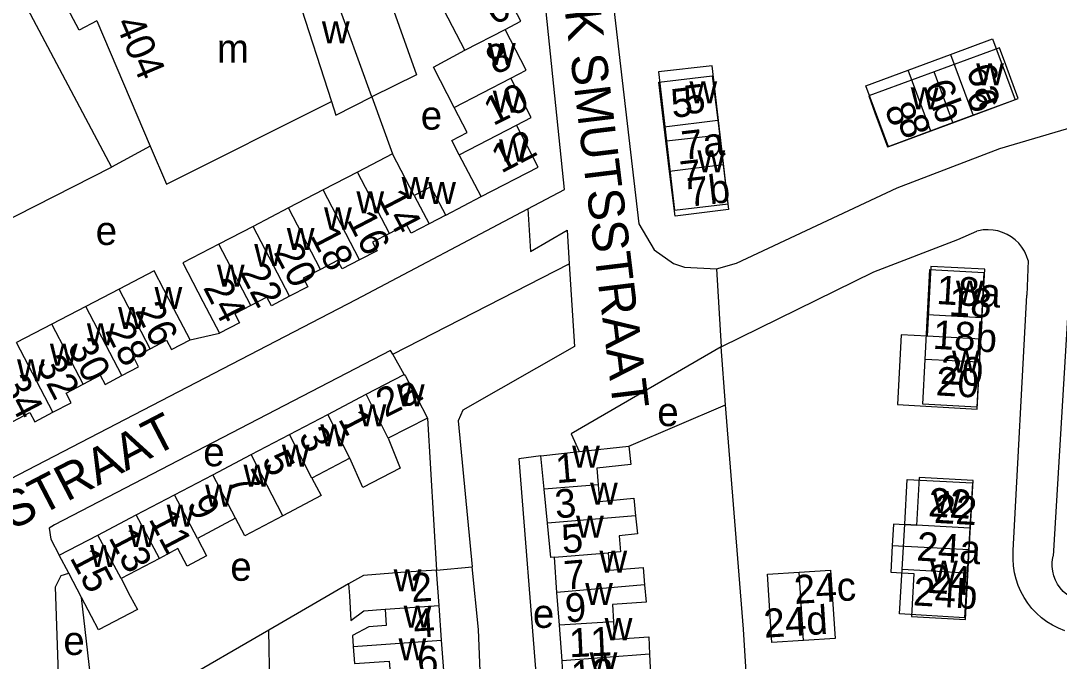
# Model space of a CAD drawing. Extents: x 163012 to 165277, y 382513 to 383987.
# Drawn here: x 163588.9 to 163733.4, y 383626.1 to 383715.3 of the extents above; entities that cross this region are included whole.
import ezdxf

# ---------------------------------------------------------------- set-up
doc = ezdxf.new("R2010")
doc.units = 0
for name, color, linetype in [('BLT_Basislijn', 7, 'Continuous'), ('BLT_Bebouwing', 7, 'Continuous'), ('BLT_Centroide', 7, 'Continuous'), ('BLT_Huisnummer', 7, 'Continuous'), ('BLT_Huisnummer_ tussenligend', 7, 'Continuous'), ('BLT_Huisnummer_zonder_bebouwing', 7, 'Continuous'), ('BLT_Onderverdeling_panden', 7, 'Continuous'), ('BLT_Plantopo', 7, 'Continuous'), ('BLT_Straatnaam', 7, 'Continuous'), ('BLT_Vlakafsluiter', 7, 'Continuous')]:
    doc.layers.add(name, color=color, linetype=linetype)

msp = doc.modelspace()

# ---------------------------------------------------------------- linework, layer by layer
at = {"layer": 'BLT_Basislijn'}
for p, q in [((163582.55, 383730.64), (163601.48, 383694.92)), ((163637.73, 383704.71), (163640.61, 383696.76)), ((163606.89, 383697.83), (163601.48, 383694.92)), ((163568.14, 383677.94), (163601.48, 383694.92)), ((163648.01, 383688.22), (163652.93, 383690.8)), ((163735.53, 383690.22), (163732.58, 383640.71)), ((163659.45, 383689.12), (163659.84, 383683.15)), ((163664.9, 383686.14), (163665.21, 383681.42)), ((163719.31, 383684.81), (163721.97, 383686.01)), ((163640.64, 383668.85), (163665.21, 383681.42)), ((163729.11, 383681.93), (163728.9, 383677.07)), ((163727.03, 383641.54), (163728.9, 383677.07)), ((163612.42, 383670.85), (163616.52, 383671.78)), ((163686.95, 383661.81), (163686.38, 383669.89)), ((163650.42, 383661.05), (163649.73, 383659.6)), ((163673.49, 383656.06), (163686.95, 383661.81)), ((163645.49, 383659.96), (163646.75, 383638.77)), ((163649.73, 383659.6), (163651.72, 383639.24)), ((163646.75, 383638.77), (163651.72, 383639.24)), ((163634.5, 383636.86), (163623.38, 383630.43)), ((163598.99, 383620.36), (163597.31, 383634.97)), ((163623.38, 383630.43), (163606.39, 383620.61)), ((163624.48, 383570.81), (163623.38, 383630.43))]:
    msp.add_line(p, q, dxfattribs=at)
for points in [[(163685.7, 383680.74), (163688.5, 383681.55), (163710.87, 383692.04), (163725.15, 383697.49), (163749.05, 383704.56), (163761.01, 383707), (163763.71, 383708.64), (163765.63, 383712.11), (163765.51, 383716.48), (163759.18, 383758.11)], [(163667.93, 383746.93), (163674.89, 383687.03), (163677.03, 383683.37), (163679.74, 383681.51), (163681.27, 383680.98), (163685.7, 383680.74)], [(163659.45, 383689.12), (163664.53, 383691.81), (163659.91, 383736.81)], [(163646.24, 383730.06), (163637.73, 383726.14), (163637.69, 383725.42), (163643.96, 383707.78), (163637.73, 383704.71)], [(163576.22, 383645.71), (163635.54, 383676.46), (163659.45, 383689.12)], [(163729.11, 383681.93), (163728.89, 383682.58), (163728.59, 383683.19), (163728.22, 383683.77), (163727.79, 383684.3), (163727.3, 383684.78), (163726.75, 383685.19), (163726.16, 383685.54), (163725.54, 383685.82), (163724.88, 383686.03), (163724.21, 383686.15), (163723.53, 383686.2), (163722.84, 383686.17), (163722.17, 383686.06), (163721.97, 383686.01)], [(163686.38, 383669.89), (163707.62, 383680.34), (163719.31, 383684.81)], [(163665.21, 383681.42), (163665.96, 383669.91), (163650.42, 383661.05)], [(163686.38, 383669.89), (163665.49, 383657.78), (163666.59, 383655.31)], [(163640.33, 383669.39), (163593.57, 383645.08), (163592.83, 383644.64), (163593.05, 383643.11), (163594.21, 383640.86)], [(163640.64, 383668.85), (163640.33, 383669.39)], [(163642.25, 383666.05), (163640.64, 383668.85)], [(163691.35, 383595.34), (163691.29, 383601.54), (163689.46, 383630.56), (163686.95, 383661.81)], [(163661.25, 383654.72), (163658.19, 383654.3), (163660.65, 383623.29), (163661.65, 383594.45)], [(163734.19, 383630.33), (163733.33, 383630.68), (163732.49, 383631.11), (163731.7, 383631.6), (163730.96, 383632.16), (163730.26, 383632.78), (163729.62, 383633.46), (163729.05, 383634.19), (163728.53, 383634.97), (163728.09, 383635.79), (163727.71, 383636.65), (163727.42, 383637.53), (163727.19, 383638.43), (163727.05, 383639.36), (163726.99, 383640.29), (163727, 383641.22), (163727.03, 383641.54)], [(163738.09, 383634.39), (163737.45, 383634.36), (163736.81, 383634.42), (163736.18, 383634.56), (163735.58, 383634.77), (163735, 383635.06), (163734.47, 383635.41), (163733.98, 383635.83), (163733.55, 383636.31), (163733.19, 383636.84), (163732.89, 383637.4), (163732.66, 383638), (163732.51, 383638.63), (163732.44, 383639.27), (163732.45, 383639.91), (163732.54, 383640.54), (163732.58, 383640.71)], [(163652.49, 383543.85), (163653.68, 383563.38), (163653.68, 383602.63), (163652.56, 383630.51), (163651.72, 383639.24)], [(163594.27, 383620.21), (163593.69, 383636.45), (163594.48, 383638.03), (163595.53, 383638.36)]]:
    msp.add_lwpolyline(points, dxfattribs=at)
at = {"layer": 'BLT_Bebouwing'}
for p, q in [((163596.99, 383714), (163586.94, 383733)), ((163599.44, 383715.3), (163596.99, 383714)), ((163599.44, 383715.3), (163606.89, 383697.83)), ((163640.61, 383696.76), (163635.74, 383694.23)), ((163643.63, 383690.97), (163640.61, 383696.76)), ((163635.74, 383694.23), (163630.95, 383691.73)), ((163630.95, 383691.73), (163626.13, 383689.22)), ((163626.13, 383689.22), (163621.21, 383686.66)), ((163648.01, 383688.22), (163645.69, 383687.01)), ((163621.21, 383686.66), (163616.43, 383684.17)), ((163602.54, 383677.93), (163597.91, 383675.52)), ((163597.91, 383675.52), (163593.19, 383673.06)), ((163593.19, 383673.06), (163588.27, 383670.5)), ((163636.96, 383663.27), (163642.25, 383666.05)), ((163631.62, 383660.47), (163636.96, 383663.27)), ((163644.02, 383662.75), (163645.49, 383659.96)), ((163626.27, 383657.67), (163631.62, 383660.47)), ((163645.49, 383659.96), (163640, 383657.18)), ((163620.93, 383654.87), (163626.27, 383657.67)), ((163661.25, 383654.72), (163666.59, 383655.31)), ((163666.59, 383655.31), (163673.49, 383656.06)), ((163615.59, 383652.07), (163620.93, 383654.87)), ((163634.69, 383654.39), (163629.38, 383651.59)), ((163661.71, 383650.07), (163661.25, 383654.72)), ((163610.25, 383649.27), (163615.59, 383652.07)), ((163604.91, 383646.47), (163610.25, 383649.27)), ((163662.17, 383645.32), (163661.71, 383650.07)), ((163599.57, 383643.67), (163604.91, 383646.47)), ((163618.76, 383646), (163613.45, 383643.2)), ((163594.21, 383640.86), (163599.57, 383643.67)), ((163595.53, 383638.36), (163594.21, 383640.86)), ((163663.5, 383635.68), (163663.14, 383640.58)), ((163608.15, 383640.41), (163602.84, 383637.61)), ((163647.1, 383633.86), (163646.75, 383638.77)), ((163663.84, 383631.13), (163663.5, 383635.68)), ((163647.44, 383629.02), (163647.1, 383633.86)), ((163664.21, 383626.15), (163663.84, 383631.13))]:
    msp.add_line(p, q, dxfattribs=at)
for points in [[(163637.73, 383704.71), (163630.85, 383723.71), (163626.49, 383721.47)], [(163656.27, 383714.09), (163658.46, 383715.22), (163655.59, 383720.75)], [(163650.67, 383711.19), (163647.8, 383716.73), (163649.84, 383717.79)], [(163657.07, 383707.3), (163659.21, 383708.41), (163656.27, 383714.09)], [(163718.61, 383701.12), (163727.72, 383704.48), (163725.99, 383709.17), (163725.12, 383711.53), (163716.01, 383708.18)], [(163649.21, 383703.22), (163646.32, 383708.81), (163650.67, 383711.19)], [(163686.22, 383699.42), (163685.1, 383709.04), (163677.64, 383708.17), (163678.76, 383698.55)], [(163657.85, 383700.74), (163659.91, 383701.81), (163657.07, 383707.3)], [(163716.01, 383708.18), (163706.9, 383704.82), (163707.77, 383702.46), (163709.5, 383697.76), (163718.61, 383701.12)], [(163632.12, 383704.04), (163632.73, 383702.14), (163637.73, 383704.71)], [(163606.89, 383697.83), (163609.13, 383692.55), (163632.12, 383704.04)], [(163649.91, 383696.63), (163648.87, 383698.63), (163651.02, 383699.74), (163649.21, 383703.22)], [(163652.93, 383690.8), (163660.87, 383694.91), (163657.85, 383700.74)], [(163678.76, 383698.55), (163679.88, 383688.93), (163687.34, 383689.8), (163686.22, 383699.42)], [(163652.93, 383690.8), (163649.91, 383696.63)], [(163648.01, 383688.22), (163645.95, 383692.17), (163643.63, 383690.97)], [(163645.69, 383687.01), (163643.19, 383685.71), (163642.55, 383686.92), (163640.19, 383685.69)], [(163640.19, 383685.69), (163637.83, 383684.46), (163638.45, 383683.26), (163636.02, 383681.99)], [(163616.43, 383684.17), (163611.43, 383681.57), (163614.21, 383676.22), (163616.52, 383671.78)], [(163636.02, 383681.99), (163633.59, 383680.73), (163632.97, 383681.92), (163630.58, 383680.67)], [(163722.52, 383670.95), (163723.06, 383680.68), (163715.57, 383681.09), (163715.03, 383671.36)], [(163612.42, 383670.85), (163610.11, 383675.29), (163607.41, 383680.47), (163602.54, 383677.93)], [(163630.58, 383680.67), (163628.19, 383679.43), (163628.81, 383678.24), (163626.27, 383676.92)], [(163626.27, 383676.92), (163623.74, 383675.6), (163623.12, 383676.8), (163620.88, 383675.63)], [(163620.88, 383675.63), (163618.64, 383674.46), (163619.29, 383673.23), (163616.52, 383671.78)], [(163715.03, 383671.36), (163711.44, 383671.56), (163710.91, 383661.83), (163721.98, 383661.22), (163722.52, 383670.95)], [(163602.93, 383665.87), (163605.27, 383667.09), (163604.58, 383668.42), (163606.87, 383669.61)], [(163606.87, 383669.61), (163609.15, 383670.8), (163609.83, 383669.5), (163612.42, 383670.85)], [(163597.55, 383664.68), (163599.93, 383665.92), (163600.59, 383664.65), (163602.93, 383665.87)], [(163642.25, 383666.05), (163642.42, 383665.78), (163644.02, 383662.75)], [(163593.34, 383660.77), (163595.87, 383662.09), (163595.17, 383663.45), (163597.55, 383664.68)], [(163587.76, 383659.48), (163590.14, 383660.73), (163590.8, 383659.45), (163593.34, 383660.77)], [(163640, 383657.18), (163641.69, 383653), (163636.49, 383650.28), (163634.69, 383654.39)], [(163673.49, 383656.06), (163673.78, 383653.48), (163669.05, 383652.99), (163669.24, 383650.67)], [(163629.38, 383651.59), (163630.66, 383649.16), (163625.35, 383646.36)], [(163720.9, 383641.59), (163721.43, 383651.26), (163716.44, 383651.54), (163713.93, 383651.68), (163713.57, 383645.01), (163710.35, 383645.18), (163710.18, 383642.18)], [(163669.24, 383650.67), (163669.42, 383648.36), (163674.2, 383648.82), (163674.45, 383646.34)], [(163625.35, 383646.36), (163620.04, 383643.57), (163618.76, 383646)], [(163663.14, 383640.58), (163662.64, 383640.54), (163662.17, 383645.32)], [(163674.45, 383646.34), (163674.7, 383643.85), (163672.15, 383643.58), (163672.33, 383641.35), (163670.62, 383641.21)], [(163613.45, 383643.2), (163614.73, 383640.77), (163612.02, 383639.35), (163610.74, 383641.78), (163608.15, 383640.41)], [(163710.18, 383642.18), (163709.98, 383638.51), (163713.19, 383638.33), (163712.86, 383632.33), (163715.37, 383632.19), (163720.36, 383631.92), (163720.9, 383641.59)], [(163670.62, 383641.21), (163670.83, 383638.79), (163675.48, 383639.17), (163675.69, 383636.75)], [(163597.31, 383634.97), (163595.53, 383638.36)], [(163646.75, 383638.77), (163641.76, 383638.45), (163636.56, 383638.03), (163634.5, 383636.86)], [(163602.84, 383637.61), (163604.11, 383635.18), (163605.1, 383633.3), (163599.69, 383630.46), (163598.7, 383632.33), (163597.31, 383634.97)], [(163634.5, 383636.86), (163634.61, 383635.2), (163634.82, 383631.77), (163636.61, 383633.11), (163639.59, 383633.33)], [(163675.69, 383636.75), (163675.9, 383634.34), (163671.23, 383633.99), (163671.37, 383631.57)], [(163639.59, 383633.33), (163639.74, 383631.06), (163637.3, 383630.91), (163635.04, 383629.66), (163635.14, 383628.15)], [(163671.37, 383631.57), (163671.51, 383629.15), (163676.27, 383629.49), (163676.38, 383627.06)], [(163647.36, 383624.16), (163647.78, 383624.19), (163647.44, 383629.02)], [(163635.14, 383628.15), (163635.3, 383625.77), (163640.15, 383626.1), (163640.32, 383623.92)], [(163664.45, 383621.52), (163664.21, 383626.15)], [(163676.38, 383627.06), (163676.6, 383622.36), (163671.94, 383622.01)]]:
    msp.add_lwpolyline(points, dxfattribs=at)
at = {"layer": 'BLT_Onderverdeling_panden'}
for p, q in [((163626.49, 383721.47), (163632.12, 383704.04)), ((163650.67, 383711.19), (163656.27, 383714.09)), ((163649.21, 383703.22), (163657.07, 383707.3)), ((163718.61, 383701.12), (163716.01, 383708.18)), ((163649.91, 383696.63), (163657.85, 383700.74)), ((163678.76, 383698.55), (163686.22, 383699.42)), ((163640.19, 383685.69), (163635.74, 383694.23)), ((163636.02, 383681.99), (163630.95, 383691.73)), ((163643.63, 383690.97), (163645.69, 383687.01)), ((163630.58, 383680.67), (163626.13, 383689.22)), ((163626.27, 383676.92), (163621.21, 383686.66)), ((163620.88, 383675.63), (163616.43, 383684.17)), ((163606.87, 383669.61), (163602.54, 383677.93)), ((163602.93, 383665.87), (163597.91, 383675.52)), ((163597.55, 383664.68), (163593.19, 383673.06)), ((163722.52, 383670.95), (163715.03, 383671.36)), ((163593.34, 383660.77), (163588.27, 383670.5)), ((163640, 383657.18), (163636.96, 383663.27)), ((163634.69, 383654.39), (163631.62, 383660.47)), ((163629.38, 383651.59), (163626.27, 383657.67)), ((163625.35, 383646.36), (163620.93, 383654.87)), ((163618.76, 383646), (163615.59, 383652.07)), ((163613.45, 383643.2), (163610.25, 383649.27)), ((163669.24, 383650.67), (163661.71, 383650.07)), ((163608.15, 383640.41), (163604.91, 383646.47)), ((163674.45, 383646.34), (163662.17, 383645.32)), ((163602.84, 383637.61), (163599.57, 383643.67)), ((163720.9, 383641.59), (163710.18, 383642.18)), ((163663.14, 383640.58), (163670.62, 383641.21)), ((163675.69, 383636.75), (163663.5, 383635.68)), ((163639.59, 383633.33), (163647.1, 383633.86)), ((163671.37, 383631.57), (163663.84, 383631.13)), ((163635.14, 383628.15), (163647.44, 383629.02)), ((163676.38, 383627.06), (163664.21, 383626.15))]:
    msp.add_line(p, q, dxfattribs=at)
at = {"layer": 'BLT_Plantopo'}
for p, q in [((163712.39, 383708.41), (163718.28, 383710.59)), ((163718.28, 383710.59), (163721.43, 383702.1)), ((163715.54, 383699.91), (163712.39, 383708.41)), ((163678.43, 383700.53), (163685.88, 383701.43)), ((163685.88, 383701.43), (163686.64, 383695.22)), ((163721.43, 383702.1), (163715.54, 383699.91)), ((163679.19, 383694.31), (163678.43, 383700.53)), ((163686.64, 383695.22), (163679.19, 383694.31)), ((163714.75, 383668.13), (163715.09, 383674.38)), ((163715.09, 383674.38), (163722.61, 383673.97)), ((163722.61, 383673.97), (163722.28, 383667.73)), ((163722.28, 383667.73), (163714.75, 383668.13)), ((163711.57, 383638.89), (163711.92, 383645.18)), ((163711.92, 383645.18), (163720.99, 383644.68)), ((163720.99, 383644.68), (163720.6, 383638.37)), ((163697.84, 383628.99), (163697.22, 383638.49)), ((163720.6, 383638.37), (163711.57, 383638.89))]:
    msp.add_line(p, q, dxfattribs=at)
for points in [[(163718.28, 383710.59), (163724.14, 383712.77), (163727.29, 383704.27), (163721.43, 383702.1)], [(163678.43, 383700.53), (163677.68, 383706.73), (163685.12, 383707.63), (163685.88, 383701.43)], [(163715.54, 383699.91), (163709.66, 383697.73), (163706.51, 383706.23), (163712.39, 383708.41)], [(163686.64, 383695.22), (163687.39, 383688.99), (163679.95, 383688.08), (163679.19, 383694.31)], [(163715.09, 383674.38), (163715.42, 383680.65), (163722.95, 383680.24), (163722.61, 383673.97)], [(163722.28, 383667.73), (163721.95, 383661.48), (163714.42, 383661.88), (163714.75, 383668.13)], [(163711.92, 383645.18), (163712.26, 383651.42), (163721.34, 383650.92), (163720.99, 383644.68)], [(163697.84, 383628.99), (163693.43, 383628.7), (163692.81, 383638.2), (163697.22, 383638.49)], [(163697.22, 383638.49), (163701.59, 383638.78), (163702.21, 383629.27), (163697.84, 383628.99)], [(163720.6, 383638.37), (163720.24, 383632.16), (163711.21, 383632.68), (163711.57, 383638.89)]]:
    msp.add_lwpolyline(points, dxfattribs=at)
at = {"layer": 'BLT_Vlakafsluiter'}
for p, q in [((163659.84, 383683.15), (163664.9, 383686.14)), ((163685.7, 383680.74), (163686.38, 383669.89))]:
    msp.add_line(p, q, dxfattribs=at)

# ---------------------------------------------------------------- texts
at = {"layer": 'BLT_Centroide'}
for s, p in [('w', (163630.78, 383712.14)), ('m', (163616.16, 383709.44)), ('w', (163653.9, 383709.12)), ('w', (163721.86, 383706.31)), ('w', (163681.94, 383703.8)), ('w', (163712.75, 383702.97)), ('w', (163654.57, 383702.5)), ('e', (163644.54, 383700.13)), ('w', (163655.45, 383695.69)), ('w', (163683.05, 383694.17)), ('w', (163641.88, 383690.45)), ('w', (163645.57, 383689.76)), ('w', (163635.58, 383688.48)), ('w', (163631.08, 383686.22)), ('e', (163599.29, 383684.07)), ('w', (163625.89, 383683.38)), ('w', (163621.36, 383681.12)), ('w', (163616.16, 383678.27)), ('w', (163607.48, 383675.14)), ('w', (163719.05, 383676.03)), ('w', (163602.39, 383672.38)), ('w', (163598.06, 383670.08)), ('w', (163592.91, 383667.25)), ('w', (163588.34, 383665.08)), ('w', (163718.5, 383666.28)), ('w', (163641.22, 383661.61)), ('w', (163635.89, 383658.81)), ('e', (163677.47, 383658.84)), ('w', (163630.55, 383656.02)), ('e', (163614.26, 383653.25)), ('w', (163625.2, 383653.2)), ('w', (163665.61, 383653.06)), ('w', (163619.86, 383650.42)), ('w', (163668.11, 383647.91)), ('w', (163614.52, 383647.61)), ('w', (163715.81, 383646.72)), ('w', (163609.17, 383644.83)), ('w', (163666.16, 383643.31)), ('w', (163603.83, 383642.02)), ('w', (163598.48, 383639.22)), ('w', (163669.42, 383638.44)), ('e', (163618.03, 383637.3)), ('w', (163715.44, 383637.05)), ('w', (163640.76, 383635.84)), ('w', (163667.43, 383633.94)), ('w', (163642.16, 383630.75)), ('e', (163660.15, 383630.74)), ('w', (163670.14, 383629.03)), ('e', (163594.79, 383626.97)), ('w', (163641.45, 383626.22)), ('w', (163668.05, 383624.28))]:
    msp.add_text(s, height=4, dxfattribs=at).set_placement(p)
at = {"layer": 'BLT_Huisnummer'}
for s, rotation, p in [('6', 26.4351, (163654.71, 383714.6)), ('404', 293.0735, (163601.95, 383714.97)), ('5', 6.6519, (163679.6, 383701.75)), ('6', 290.2279, (163720.38, 383704.96)), ('8', 290.2288, (163710.9, 383701.36)), ('12', 27.3991, (163655.74, 383693.99)), ('7', 6.6443, (163680.86, 383691.71)), ('14', 297.5101, (163638.52, 383690.55)), ('18', 297.509, (163629.08, 383685.39)), ('24', 297.5045, (163614.18, 383678.14)), ('18', 356.8346, (163717.99, 383674.27)), ('26', 297.4942, (163604.66, 383674.9)), ('30', 297.4955, (163595.27, 383669.88)), ('20', 356.8426, (163716.79, 383664.73)), ('34', 297.4974, (163585.89, 383664.76)), ('2a', 26.5957, (163639.61, 383659.97)), ('1', 297.6575, (163632.98, 383659.85)), ('5', 297.654, (163622.31, 383654.13)), ('1', 4.5791, (163663.45, 383650.89)), ('9', 297.6579, (163611.89, 383648.04)), ('22', 356.8376, (163715.94, 383645.38)), ('5', 5.013, (163664.31, 383641.09)), ('15', 297.7654, (163595.62, 383640.54)), ('24', 356.8469, (163715.06, 383635.62)), ('2', 3.6784, (163643.29, 383634.32)), ('9', 2.6477, (163664.69, 383631.52)), ('6', 2.0075, (163644.09, 383624.18)), ('13', 3.6877, (163665.59, 383622.17))]:
    msp.add_text(s, height=4, rotation=rotation, dxfattribs=at).set_placement(p)
at = {"layer": 'BLT_Huisnummer_ tussenligend'}
for s, rotation, p in [('8', 26.4351, (163654.91, 383707.68)), ('10', 26.4351, (163654.62, 383700.6)), ('16', 297.5101, (163634.17, 383687.58)), ('20', 297.509, (163624, 383683.08)), ('22', 297.509, (163619.25, 383680.29)), ('28', 297.4942, (163600.51, 383672.12)), ('32', 297.4955, (163590.93, 383667.49)), ('3', 297.6575, (163627.43, 383657.47)), ('7', 297.654, (163617.56, 383651.37)), ('3', 4.5791, (163663.35, 383645.98)), ('11', 297.6579, (163606.6, 383645.93)), ('13', 297.6618, (163601.02, 383643.34)), ('7', 5.013, (163664.64, 383636.04)), ('4', 3.6784, (163643.63, 383629.33)), ('11', 2.6477, (163665.26, 383626.64))]:
    msp.add_text(s, height=4, rotation=rotation, dxfattribs=at).set_placement(p)
at = {"layer": 'BLT_Huisnummer_zonder_bebouwing'}
for s, rotation, p in [('6a', 290.5724, (163720.41, 383708.47)), ('5', 6.5724, (163681.39, 383702.24)), ('6b', 290.5724, (163714.56, 383706.26)), ('8', 290.5724, (163709.06, 383703.1)), ('7a', 6.5724, (163681.06, 383695.9)), ('7b', 6.5724, (163681.86, 383689.38)), ('18a', 356.5724, (163716.25, 383675.86)), ('18b', 356.5724, (163715.74, 383669.63)), ('20', 356.5724, (163716.18, 383663.14)), ('22', 356.5724, (163715.11, 383646.29)), ('24a', 356.5724, (163713.49, 383640.13)), ('24c', 3.5724, (163696.62, 383634.06)), ('24b', 356.5724, (163713.02, 383633.89)), ('24d', 3.5724, (163692.39, 383629.36))]:
    msp.add_text(s, height=4, rotation=rotation, dxfattribs=at).set_placement(p)
at = {"layer": 'BLT_Straatnaam'}
for s, rotation, p in [('VELDMAARSCHALK SMUTSSTRAAT', 276.9537, (163657.43, 383775.37)), ('TAFELBERGSTRAAT', 27.4675, (163552.39, 383625.97))]:
    msp.add_text(s, height=5, rotation=rotation, dxfattribs=at).set_placement(p)

doc.saveas('drawing.dxf')
